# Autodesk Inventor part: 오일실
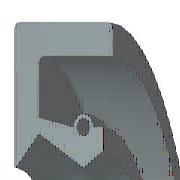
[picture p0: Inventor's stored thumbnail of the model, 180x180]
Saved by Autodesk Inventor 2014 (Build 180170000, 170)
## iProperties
IsCustomPart: 0
Created: 2014-10
Part Number: 오일실
Material: 고무
Description: 오일-실
Document SubType Name: Modeling
Standard: KS B 2804
Designer: KYOUNG IL JANG
Standards Organization: KS
Language: ko-KR
Size Designation: D - 17 32 8
Categories: <MemberInstance><Categories><Category DisplayName="샤프트 부품" InternalName="7f7aeb1f-a693-4053-b835-cee3144e0d98" Mnemonic="SHFT"><Category DisplayName="실링" Intern
Density: 0.93 g/cm^3
Mass: 2.28027 g
Surface Area: 32.1224 cm^2
Volume: 2.45191 cm^3
Appearance: 고무 - 검은색 - 버전 1.1
Author: SeoGD™ [www.esajin.kr]
Revision Number: 1
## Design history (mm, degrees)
revolve "본체" stored, may be unused: angle "d17" = 90 deg
revolve "스프링1" stored, may be unused: angle "d18" = 90 deg
body "Solid1"
sketch "스케치1"
  geometry: L1 (0, 16)-(8, 16); L2 (8, 14.25)-(1.75, 14.25); L3 (1.75, 10.25)-(4.9, 8.5); L4 (4.9, 8.5)-(0, 8.5); L5 (0, 0)-(9.586, 0) reference; L6 (4.9, 8.5)-(6.3, 9.375); L7 (0, 18)-(0, -3) reference; L8 (-1.941, 0)-(11.507, 0) reference; L9 (4.2, 10.6)-(1.75, 11.21); L10 (1.75, 11.21)-(1.75, 14.25); L11 (0, 16)-(0, 8.588); L12 (4.9, 8.5)-(0, 8.5); L13 (1.75, 10.25)-(0.152, 8.528); L14 (8, 16)-(8, 14.25); L15 (5.6, 10.6)-(6.3, 10.6); L16 (6.3, 10.6)-(6.3, 9.375); C1 r 0.455 at (4.9, 10.6); A1 r 0.7 centre (4.9, 10.6) between (5.6, 10.6) and (4.2, 10.6); A2 r 0.088 centre (0.088, 8.588) between (0, 8.588) and (0.152, 8.528); 1 further point
  constraints: 28 end point, 5 horizontal alignment, 5 point on line, 4 point on circle, 4 vertical alignment, 3 centre point, 3 tangent, 2 collinear, 2 horizontal, 2 perpendicular, 1 coincident, 1 parallel
  dimensions: "d0" = 32 diameter of L1 L5 (= SD2); "d1" = 1.75 distance of L1.end L2.start (= SD); "d2" = 0.91 diameter of C1 (= SPDI); "d3" = 1.4 diameter of A1 (= SPDA); "d4" = 17 diameter of L3.end L5 (= NND); "d5" = 20.5 diameter of L3.start L5 (= TKDM); "d7" = 22.42 diameter of L9.end L5 (= TKDM + 0.24 x SWDT); "d8" = 1.75 distance between parallel lines of L11 L10 (= SD); "d9" = 4.9 distance from line of L11 C1.centre (= SPDST); "d10" = 21.2 diameter of C1.centre L5 (= HLDM); "d11" = 0.0875 radius of A2 (= 0.25 x LAB); "d12" = 6.3 distance between parallel lines of L11 L16 (= SDI); "d13" = 18.75 diameter of L6.end L5 (= ABDM); "d14" = 8 distance from line of L11 L1.end (= SWDT)
fillet "모깎기1" dims "d6" = 0.3 (= RR)
other parameters: "SD2" = 32 [user parameter; used in 1 equation term], "SWDT" = 8 [user parameter; used in 2 equation terms], "RR" = 0.3 [user parameter; used in 1 equation term], "SD" = 1.75 [user parameter; used in 2 equation terms], "NND" = 17 [user parameter; used in 1 equation term], "SPDA" = 1.4 [user parameter; used in 1 equation term], "SPDI" = 0.91 [user parameter; used in 1 equation term], "TKDM" = 20.5 [user parameter; used in 2 equation terms], "HLDM" = 21.2 [user parameter; used in 1 equation term], "ABDM" = 18.75 [user parameter; used in 1 equation term], "SDI" = 6.3 [user parameter; used in 1 equation term], "SPDST" = 4.9 [user parameter; used in 1 equation term], "LAB" = 0.35 [user parameter; used in 1 equation term], "d15" = 0, "d16" = 0, "d19" = 0
